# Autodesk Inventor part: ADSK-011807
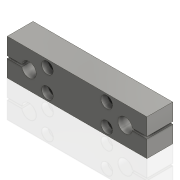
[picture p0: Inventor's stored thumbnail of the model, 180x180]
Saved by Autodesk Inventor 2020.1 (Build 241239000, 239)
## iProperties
Created: 1999-12
Part Number: ADSK-011807
Material: Aluminum
Description: TOOL PLATE_SD22
Document SubType Name: Modeling
Designer: glanglot
Density: 2.71 g/cm^3
Appearance: Steel
Mass: 102.448 g
Surface Area: 115.773 cm^2
Volume: 37.8036 cm^3
Control State: 0
Master: False
Checked Out: False
Shininess: 0.0
Length Units: 11269
Angle Units: 11279
Time Units: 11290
Mass Units: 11283
Length Display Precision: 3
Angle Display Precision: 2
Compacted: True
Dimensions: 96,5x25x17,8 mm
Mass: 0,102 kg
Density: 0.0
Volumn: 0.0
Area: 0.0
PropertySet Name: Model Information
Author: glanglot
Revision Number: -
Title: TOOL PLATE_SD22
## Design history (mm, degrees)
node "Extrusion1" dims "d2" = 17.78, "d3" = 0
  sketch "Sketch1"
    geometry: L1 (-48.25, 12.5)-(48.25, 12.5); L2 (48.25, 12.5)-(48.25, -12.5); L3 (48.25, -12.5)-(-48.25, -12.5); L4 (-48.25, -12.5)-(-48.25, 12.5); 3 further points
    constraints: 8 end point, 2 midpoint, 2 parallel, 1 horizontal, 1 horizontal alignment, 1 perpendicular, 1 vertical alignment
    dimensions: "d0" = 25 distance of L3.end L1.start; "d1" = 96.5 distance of L2.end L3.end
node "Hole1" dims "d8" = 4.5, "d9" = 8, "d10" = 4.6, "d11" = 60 deg, "d12" = 19.05, "d13" = 118 deg, "d48" = 12.7
  sketch "Sketch2"
    geometry: L1 (-48.25, 12.5)-(48.25, 12.5) reference; L2 (-48.25, -12.5)-(-48.25, 12.5) reference; L3 (-20.5, 7.5)-(20.5, 7.5); L4 (20.5, 7.5)-(20.5, -7.5); L5 (20.5, -7.5)-(-20.5, -7.5); L6 (-20.5, -7.5)-(-20.5, 7.5); 6 further points
    constraints: 8 end point, 4 midpoint, 3 horizontal alignment, 3 vertical alignment, 2 parallel, 1 horizontal, 1 perpendicular
    dimensions: "d42" = 41 distance of L3.start L3.end; "d43" = 15 distance of L5.end L3.start
node "Hole2" dims "d17" = 10, "d18" = 11.1125, "d19" = 6.985, "d20" = 60 deg, "d21" = 19.05, "d22" = 118 deg, "d45" = 6
  sketch "Sketch3"
    geometry: L1 (-48.25, 12.5)-(48.25, 12.5) reference; L2 (-48.25, -12.5)-(-48.25, 12.5) reference; L3 (-33.25, 0)-(33.25, 0); 3 further points
    constraints: 3 midpoint, 2 end point, 2 horizontal alignment, 1 horizontal, 1 vertical alignment
    dimensions: "d44" = 66.5 distance of L3.start L3.end
node "Extrusion4" dims "d32" = 25.4, "d33" = 0
  sketch "Sketch6"
    geometry: L1 (-16.8, 12.5)-(0, 12.5); L2 (-17.78, 13.25)-(0, 13.25); L3 (-17.78, 11.75)-(0, 11.75); L4 (-17.78, 13.25)-(-17.78, 11.75) reference; L5 (0, 13.25)-(0, 11.75); L6 (0, 0)-(0, 25) reference; 1 further point
    constraints: 10 end point, 2 midpoint, 1 collinear, 1 parallel, 1 perpendicular, 1 vertical
    dimensions: "d46" = 1.5 distance between parallel lines of L3 L2; "d47" = 0.75 distance between parallel lines of L1 L2 (= 0.5 x d46)
mirror "Spiegeln1"
node "Solide1"
node "Corps solides"
node "Corps surfaciques"
